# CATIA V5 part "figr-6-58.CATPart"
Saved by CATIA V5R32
Part number: Part1
Bounding box of the stored display mesh (mm): x -50.648 to 73.742, y -72.183 to 95.277, z -40 to 40
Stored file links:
  D:\PROJECTS\Project 2022\CATIA V5 6R 2022\Resources\Part Files\c06_catia_v5_6r2022_prt\figr-6-58.CATPart
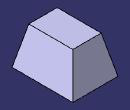
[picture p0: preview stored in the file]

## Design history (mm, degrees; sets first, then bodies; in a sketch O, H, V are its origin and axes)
Body1 (main body)
  Sketch1 on xy-plane, origin (0, 0, 0), H (1, 0, 0), V (0, 1, 0)
    line L1 (-50.6478, 72.1832) -> (50.6478, 72.1832)
    line L2 (50.6478, 72.1832) -> (50.6478, -72.1832)
    line L3 (50.6478, -72.1832) -> (-50.6478, -72.1832)
    line L4 (-50.6478, -72.1832) -> (-50.6478, 72.1832)
    axis line L5 (50.6478, -72.1832) -> (-50.6478, 72.1832)
    horizontal: L1 H, L3 H
    vertical: L2 V, L4 V
    midpoint: O L5
  Pad1: profile Sketch1, direction (0, 0, 1), length 40, mirrored extent
  Draft1: Angle 30, Neutral xy-plane, PullDir (0, 0, 1), SupportToDraft (face of Pad1; face of Pad1)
